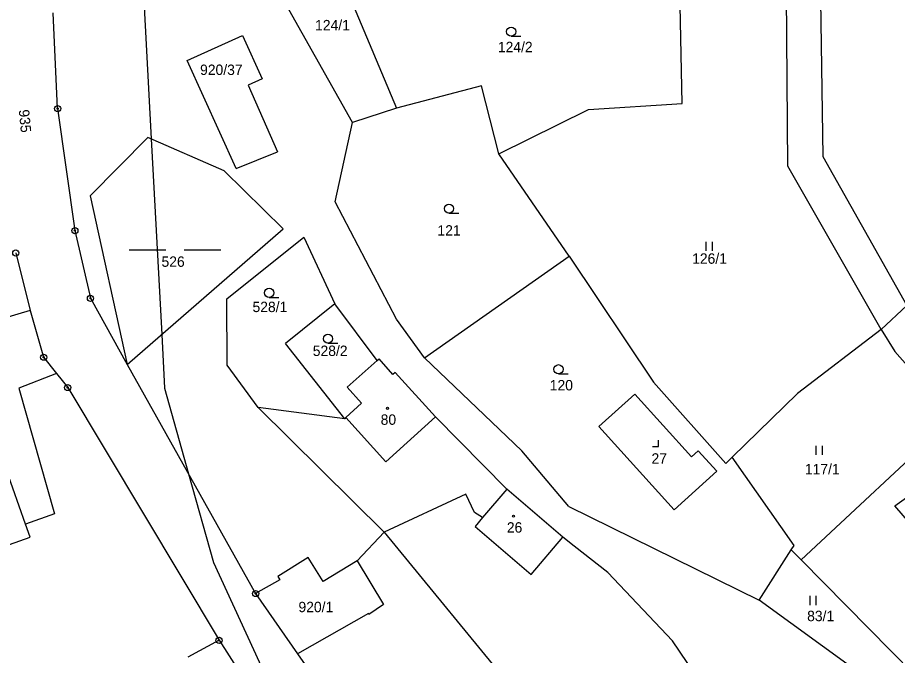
# Model space of a CAD drawing. Extents: x -547623 to -538651, y -1096714 to -1086522.
# Drawn here: x -544649.1 to -544505.1, y -1093186.7 to -1093082.4 of the extents above; entities that cross this region are included whole.
import ezdxf

# ---------------------------------------------------------------- set-up
doc = ezdxf.new("R2010")
doc.units = 0
for name, color, linetype in [('Vrstva 1', 7, 'Continuous'), ('Vrstva 25', 7, 'Continuous'), ('Vrstva 33', 7, 'Continuous'), ('Vrstva 52', 7, 'Continuous'), ('Vrstva 83', 7, 'Continuous'), ('Vrstva 86', 7, 'Continuous'), ('Vrstva 90', 7, 'Continuous'), ('Vrstva 92', 7, 'Continuous')]:
    doc.layers.add(name, color=color, linetype=linetype)

msp = doc.modelspace()

# ---------------------------------------------------------------- linework, layer by layer
at = {"layer": 'Vrstva 1'}
for points in [[(-544597.28, -1093072.77), (-544587.03, -1093097.19)], [(-544594.26, -1093099.51), (-544608.56, -1093074.11)], [(-544517.73, -1093075.81), (-544517.31, -1093105.09)], [(-544522.99, -1093106.65), (-544523.22, -1093078.47)], [(-544540.3, -1093096.41), (-544540.61, -1093080.38)], [(-544642.5, -1093097.25), (-544643.21, -1093081.57)], [(-544621.28, -1093089.36), (-544612.23, -1093085.28)], [(-544612.23, -1093085.28), (-544609.03, -1093092.37)], [(-544613.31, -1093107.03), (-544621.28, -1093089.36)], [(-544609.03, -1093092.37), (-544611.35, -1093093.4)], [(-544611.35, -1093093.4), (-544606.54, -1093104.32)], [(-544573.12, -1093093.53), (-544587.03, -1093097.19)], [(-544570.31, -1093104.63), (-544573.12, -1093093.53)], [(-544555.61, -1093097.38), (-544540.3, -1093096.41)], [(-544642.5, -1093097.25), (-544639.68, -1093117.22)], [(-544587.03, -1093097.19), (-544594.26, -1093099.51)], [(-544570.31, -1093104.63), (-544555.61, -1093097.38)], [(-544597.09, -1093112.49), (-544594.26, -1093099.51)], [(-544627.72, -1093101.99), (-544637.16, -1093111.53)], [(-544615.24, -1093107.44), (-544627.72, -1093101.99)], [(-544613.31, -1093107.03), (-544606.54, -1093104.32)], [(-544558.78, -1093121.39), (-544570.31, -1093104.63)], [(-544517.31, -1093105.09), (-544503.53, -1093129.49)], [(-544605.57, -1093116.9), (-544615.24, -1093107.44)], [(-544507.76, -1093133.4), (-544522.99, -1093106.65)], [(-544637.16, -1093111.53), (-544631.1, -1093139.11)], [(-544587.06, -1093131.68), (-544597.09, -1093112.49)], [(-544639.68, -1093117.22), (-544637.13, -1093128.29)], [(-544631.1, -1093139.11), (-544605.57, -1093116.9)], [(-544614.83, -1093128.39), (-544602.2, -1093118.31)], [(-544602.2, -1093118.31), (-544597.12, -1093129.18)], [(-544649.35, -1093120.88), (-544647, -1093130.27)], [(-544582.48, -1093138.02), (-544558.78, -1093121.39)], [(-544558.78, -1093121.39), (-544544.97, -1093142.04)], [(-544637.13, -1093128.29), (-544631.1, -1093139.11)], [(-544614.75, -1093139.22), (-544614.83, -1093128.39)], [(-544597.12, -1093129.18), (-544605.23, -1093135.71)], [(-544590.19, -1093138.49), (-544597.12, -1093129.18)], [(-544503.53, -1093129.49), (-544507.76, -1093133.4)], [(-544647, -1093130.27), (-544651.59, -1093131.65)], [(-544647, -1093130.27), (-544644.79, -1093137.94)], [(-544582.48, -1093138.02), (-544587.06, -1093131.68)], [(-544507.76, -1093133.4), (-544521.41, -1093143.87)], [(-544507.76, -1093133.4), (-544505.51, -1093136.99)], [(-544595.5, -1093147.99), (-544605.23, -1093135.71)], [(-544644.79, -1093137.94), (-544642.7, -1093140.58)], [(-544590.19, -1093138.49), (-544589.86, -1093138.2)], [(-544587.63, -1093140.74), (-544589.86, -1093138.2)], [(-544566.52, -1093153.24), (-544582.48, -1093138.02)], [(-544505.51, -1093136.99), (-544495.89, -1093147.83)], [(-544631.1, -1093139.11), (-544610.1, -1093176.6)], [(-544609.69, -1093146.14), (-544614.75, -1093139.22)], [(-544595.1, -1093142.82), (-544590.19, -1093138.49)], [(-544642.7, -1093140.58), (-544648.84, -1093143)], [(-544642.7, -1093140.58), (-544640.86, -1093142.9)], [(-544587.27, -1093140.41), (-544587.63, -1093140.74)], [(-544580.68, -1093147.71), (-544587.27, -1093140.41)], [(-544544.97, -1093142.04), (-544533.18, -1093155.3)], [(-544648.84, -1093143), (-544643.02, -1093163.53)], [(-544640.86, -1093142.9), (-544616.09, -1093184.25)], [(-544595.1, -1093142.82), (-544592.77, -1093145.47)], [(-544553.93, -1093149.28), (-544548.05, -1093143.96)], [(-544548.05, -1093143.96), (-544538.77, -1093154.22)], [(-544521.41, -1093143.87), (-544532.11, -1093154.27)], [(-544609.69, -1093146.14), (-544589.06, -1093166.58)], [(-544595.5, -1093147.99), (-544609.69, -1093146.14)], [(-544592.77, -1093145.47), (-544595.33, -1093147.82)], [(-544595.33, -1093147.82), (-544595.5, -1093147.99)], [(-544580.68, -1093147.71), (-544569.01, -1093159.53)], [(-544495.89, -1093147.83), (-544520.83, -1093171.11)], [(-544541.62, -1093162.89), (-544553.93, -1093149.28)], [(-544647.75, -1093165.23), (-544651.96, -1093153.48)], [(-544558.83, -1093162.36), (-544566.52, -1093153.24)], [(-544538.77, -1093154.22), (-544537.68, -1093153.23)], [(-544537.68, -1093153.23), (-544534.64, -1093156.59)], [(-544532.11, -1093154.27), (-544533.18, -1093155.3)], [(-544521.96, -1093168.72), (-544532.11, -1093154.27)], [(-544505.51, -1093162.25), (-544495.89, -1093155.39)], [(-544534.64, -1093156.59), (-544541.62, -1093162.89)], [(-544569.01, -1093159.53), (-544572.98, -1093164.18)], [(-544559.81, -1093167.39), (-544569.01, -1093159.53)], [(-544575.73, -1093160.35), (-544589.06, -1093166.58)], [(-544574.26, -1093163.35), (-544575.73, -1093160.35)], [(-544558.83, -1093162.36), (-544527.7, -1093177.67)], [(-544485.76, -1093185.17), (-544505.51, -1093162.25)], [(-544643.02, -1093163.53), (-544647.75, -1093165.23)], [(-544572.98, -1093164.18), (-544574.26, -1093163.35)], [(-544646.99, -1093167.35), (-544647.75, -1093165.23)], [(-544572.98, -1093164.18), (-544574.2, -1093165.61)], [(-544589.06, -1093166.58), (-544593.49, -1093171.26)], [(-544589.06, -1093166.58), (-544567.42, -1093192.94)], [(-544574.2, -1093165.61), (-544565, -1093173.47)], [(-544652.12, -1093169.17), (-544646.99, -1093167.35)], [(-544565, -1093173.47), (-544559.81, -1093167.39)], [(-544557.98, -1093168.83), (-544559.81, -1093167.39)], [(-544552.46, -1093173.17), (-544557.98, -1093168.83)], [(-544527.7, -1093177.67), (-544522.44, -1093169.47)], [(-544522.44, -1093169.47), (-544521.96, -1093168.72)], [(-544522.44, -1093169.47), (-544520.83, -1093171.11)], [(-544601.51, -1093170.68), (-544606.48, -1093173.82)], [(-544599.04, -1093174.64), (-544601.51, -1093170.68)], [(-544593.49, -1093171.26), (-544599.04, -1093174.64)], [(-544593.49, -1093171.26), (-544589.15, -1093178.39)], [(-544520.83, -1093171.11), (-544498.72, -1093193.5)], [(-544606.48, -1093173.82), (-544606.15, -1093174.35)], [(-544541.91, -1093184.33), (-544552.46, -1093173.17)], [(-544606.15, -1093174.35), (-544610.1, -1093176.6)], [(-544610.1, -1093176.6), (-544603.25, -1093186.44)], [(-544589.15, -1093178.39), (-544591.55, -1093180.01)], [(-544486.24, -1093207.77), (-544527.7, -1093177.67)], [(-544591.65, -1093179.89), (-544603.25, -1093186.44)], [(-544591.55, -1093180.01), (-544591.65, -1093179.89)], [(-544616.09, -1093184.25), (-544621.18, -1093187)], [(-544616.09, -1093184.25), (-544610.42, -1093193.09)], [(-544522.34, -1093213.17), (-544541.91, -1093184.33)], [(-544603.25, -1093186.44), (-544595.83, -1093197.1)]]:
    msp.add_lwpolyline(points, dxfattribs=at)
at = {"layer": 'Vrstva 25'}
for p, q in [((-544568.28, -1093085.41), (-544566.68, -1093085.41)), ((-544578.46, -1093114.37), (-544576.86, -1093114.37)), ((-544536.35, -1093120.54), (-544536.35, -1093119.04)), ((-544535.35, -1093120.54), (-544535.35, -1093119.04)), ((-544630.79, -1093120.37), (-544624.79, -1093120.37)), ((-544621.79, -1093120.37), (-544615.79, -1093120.37)), ((-544607.89, -1093128.15), (-544606.29, -1093128.15)), ((-544598.27, -1093135.66), (-544596.67, -1093135.66)), ((-544560.54, -1093140.65), (-544558.94, -1093140.65)), ((-544518.36, -1093153.91), (-544518.36, -1093152.41)), ((-544517.36, -1093153.91), (-544517.36, -1093152.41)), ((-544519.37, -1093178.49), (-544519.37, -1093176.99)), ((-544518.37, -1093178.49), (-544518.37, -1093176.99))]:
    msp.add_line(p, q, dxfattribs=at)
msp.add_lwpolyline([(-544545.16, -1093152.53), (-544544.16, -1093152.53), (-544544.16, -1093151.53)], dxfattribs=at)
for centre, radius in [((-544568.28, -1093084.66), 0.75), ((-544578.46, -1093113.62), 0.75), ((-544607.89, -1093127.4), 0.75), ((-544598.27, -1093134.91), 0.75), ((-544560.54, -1093139.9), 0.75), ((-544588.53, -1093146.29), 0.175), ((-544567.91, -1093163.93), 0.175)]:
    msp.add_circle(centre, radius, dxfattribs=at)
at = {"layer": 'Vrstva 33'}
for points in [[(-544595.33, -1093147.82), (-544588.81, -1093155.04)], [(-544588.81, -1093155.04), (-544580.68, -1093147.71)]]:
    msp.add_lwpolyline(points, dxfattribs=at)
at = {"layer": 'Vrstva 52'}
msp.add_lwpolyline([(-544636, -1092993.5), (-544635.42, -1093000), (-544634.72, -1093007.89), (-544632.42, -1093033.87), (-544632.25, -1093035.72), (-544631.37, -1093045.71), (-544631.29, -1093046.58), (-544631.11, -1093048.6), (-544629.55, -1093066.22), (-544629.02, -1093072.17), (-544628.5, -1093078), (-544628.42, -1093079.58), (-544627.2, -1093102.22), (-544625.47, -1093134.21), (-544625, -1093143), (-544621.06, -1093157.03), (-544617, -1093171.5), (-544603, -1093202)], dxfattribs=at)
at = {"layer": 'Vrstva 83'}
for centre, radius in [((-544642.5, -1093097.25), 0.5), ((-544642.5, -1093097.25), 0.1), ((-544639.68, -1093117.22), 0.5), ((-544639.68, -1093117.22), 0.1), ((-544649.35, -1093120.88), 0.5), ((-544637.13, -1093128.29), 0.5), ((-544637.13, -1093128.29), 0.1), ((-544644.79, -1093137.94), 0.5), ((-544644.79, -1093137.94), 0.1), ((-544640.86, -1093142.9), 0.5), ((-544640.86, -1093142.9), 0.1), ((-544610.1, -1093176.6), 0.5), ((-544610.1, -1093176.6), 0.1), ((-544616.09, -1093184.25), 0.5), ((-544616.09, -1093184.25), 0.1)]:
    msp.add_circle(centre, radius, dxfattribs=at)
at = {"layer": 'Vrstva 90'}
for points in [[(-544590.19, -1093138.49), (-544589.86, -1093138.2)], [(-544587.63, -1093140.74), (-544589.86, -1093138.2)], [(-544595.1, -1093142.82), (-544590.19, -1093138.49)], [(-544587.27, -1093140.41), (-544587.63, -1093140.74)], [(-544580.68, -1093147.71), (-544587.27, -1093140.41)], [(-544595.1, -1093142.82), (-544592.77, -1093145.47)], [(-544592.77, -1093145.47), (-544595.33, -1093147.82)], [(-544595.33, -1093147.82), (-544588.81, -1093155.04)], [(-544588.81, -1093155.04), (-544580.68, -1093147.71)], [(-544647.75, -1093165.23), (-544651.96, -1093153.48)], [(-544569.01, -1093159.53), (-544572.98, -1093164.18)], [(-544559.81, -1093167.39), (-544569.01, -1093159.53)], [(-544646.99, -1093167.35), (-544647.75, -1093165.23)], [(-544572.98, -1093164.18), (-544574.2, -1093165.61)], [(-544574.2, -1093165.61), (-544565, -1093173.47)], [(-544652.12, -1093169.17), (-544646.99, -1093167.35)], [(-544565, -1093173.47), (-544559.81, -1093167.39)]]:
    msp.add_lwpolyline(points, dxfattribs=at)

# ---------------------------------------------------------------- texts
at = {"layer": 'Vrstva 86'}
for s, p in [('124/1', (-544600.37, -1093084.45)), ('124/2', (-544570.46, -1093088.03)), ('920/37', (-544619.19, -1093091.75)), ('121', (-544580.35, -1093118.03)), ('126/1', (-544538.67, -1093122.64)), ('526', (-544625.5, -1093123.14)), ('528/1', (-544610.61, -1093130.55)), ('528/2', (-544600.75, -1093137.73)), ('120', (-544561.97, -1093143.36)), ('117/1', (-544520.22, -1093157.09)), ('920/1', (-544603.09, -1093179.65)), ('83/1', (-544519.85, -1093181.12))]:
    msp.add_text(s, height=1.7, dxfattribs=at).set_placement(p)
msp.add_text('935', height=1.7, rotation=275.5812, dxfattribs=at).set_placement((-544648.87, -1093097.48))
at = {"layer": 'Vrstva 92'}
for s, p in [('80', (-544589.64, -1093148.99)), ('27', (-544545.32, -1093155.35)), ('26', (-544568.99, -1093166.63))]:
    msp.add_text(s, height=1.7, dxfattribs=at).set_placement(p)

doc.saveas('drawing.dxf')
